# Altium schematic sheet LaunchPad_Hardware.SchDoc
size 431 x 279 mm; Date: Not shown in title block; ApprovedBy: Not shown in title block; CheckedBy: Not shown in title block; Author: Not shown in title block; CompanyName: Not shown in title block; Engineer: Not shown in title block; Organization: Not shown in title block; Address1: Not shown in title block; Address2: Not shown in title block; Address3: Not shown in title block; Address4: Not shown in title block; DocumentNumber: 1; Revision: Use project parameter SCH_Rev; SheetNumber: 2; SheetTotal: 3; PageSetup: Record=PageOptions¦CenterHorizontal=True¦CenterVertical=True¦PrintScale=1.00¦XCorrection=1.00¦YCorrection=1.00¦PrintKind=0¦BorderSize=5000000¦LeftOffset=0¦BottomOffset=0¦Orientation=2¦PaperLength=1000¦PaperWidth=1000¦Scale=100¦PaperSource=15¦PrintQuality=600¦MediaType=1¦DitherType=10¦PaperKind=Letter¦PrintScaleMode=1
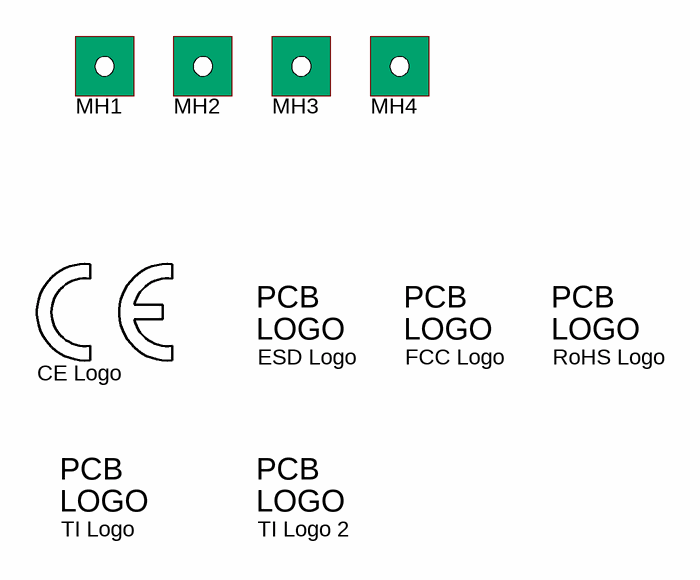
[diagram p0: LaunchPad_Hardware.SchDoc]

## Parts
CE_Logo  CE Mark  [CE_Mark_5mm]  (value not drawn)  (no BOM)
ESD_Logo  ESD Susceptible  [ESD_Overlay_Medium]  (value not drawn)  (no BOM)
FCC_Logo  FCC disclaimer  [FCC_disclaimer]  (value not drawn)  (no BOM)
MH1  MTG_NoPads  [NPTH125mil]  (value not drawn)  (no BOM)
MH2  MTG_NoPads  [NPTH125mil]  (value not drawn)  (no BOM)
MH3  MTG_NoPads  [NPTH125mil]  (value not drawn)  (no BOM)
MH4  MTG_NoPads  [NPTH125mil]  (value not drawn)  (no BOM)
RoHS_Logo  Pb-Free Symbol  [Pb-Free_Overlay_Medium]  (value not drawn)  (no BOM)
TI_Logo  Texas Instruments  [TI_Symbol_Overlay_Medium]  (value not drawn)  (no BOM)
TI_Logo_2  Texas Instruments  [TI_Horizontal_Overlay_Small]  (value not drawn)  (no BOM)

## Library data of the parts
CE_Logo = CE Mark: SymbolCreator: a0412235
ESD_Logo = ESD_Susceptible: ESD Susceptible Symbol; SymbolCreator: a0412235
FCC_Logo = FCC_disclaimer: SymbolCreator: a0412235
MH1-MH4 = Mounting Hole (non-standard) No Pad: PCB Mounting Hole, No Pad; Manufacturer: Any; SymbolCreator: a0412235
RoHS_Logo = Pb-Free: SymbolCreator: a0412235
TI_Logo TI_Logo_2 = TI_Logo: Texas Instrument Corporate Signature; SymbolCreator: a0412235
